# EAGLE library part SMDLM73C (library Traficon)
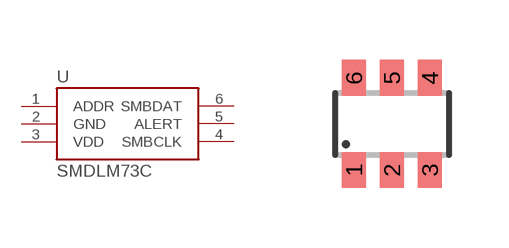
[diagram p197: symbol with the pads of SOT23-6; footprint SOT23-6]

Designator prefix U

## SMDLM73C  [SOT23-6]
1  ADDR  in
2  GND  sup
3  VDD  sup
4  SMBCLK  in
5  ALERT  out
6  SMBDAT

## Footprint SOT23-6 (pad centres in mm)
Small Outline Transistor 6 lead
smd 0.6 x 0.9: 1 -0.95,-1.15; 2 0,-1.15; 3 0.95,-1.15; 4 0.95,1.15; 5 0,1.15; 6 -0.95,1.15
